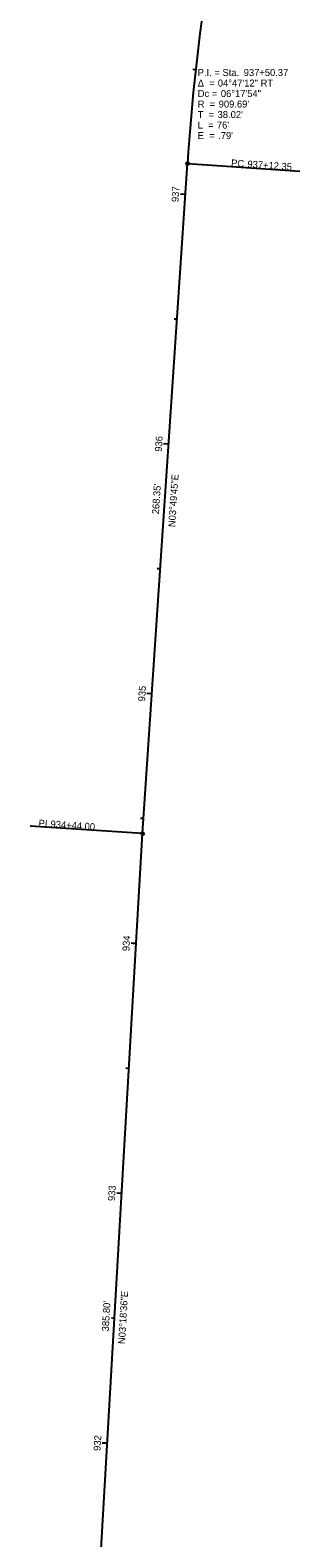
# Model space of a CAD drawing. Extents: x 1978725 to 1979446, y 230316 to 232755.
# Drawn here: x 1978725 to 1978833, y 230920 to 231522 of the extents above; entities that cross this region are included whole.
import ezdxf

# ---------------------------------------------------------------- set-up
doc = ezdxf.new("R2010")
doc.units = 0
for name, color, linetype in [('GE_X_Alignment', 7, 'Continuous'), ('GE_X_Alignment_1000_Curve_Data', 7, 'Continuous'), ('GE_X_Alignment_1000_Stations', 7, 'Continuous'), ('GE_X_Alignment_100_Curve_Data', 7, 'Continuous'), ('GE_X_Alignment_100_Stations', 7, 'Continuous'), ('GE_X_Alignment_500_Curve_Data', 7, 'Continuous'), ('GE_X_Alignment_500_Stations', 7, 'Continuous')]:
    doc.layers.add(name, color=color, linetype=linetype)

msp = doc.modelspace()

# ---------------------------------------------------------------- linework, layer by layer
at = {"layer": 'GE_X_Alignment'}
for p, q in [((1978770.14, 231201.33), (1978788.06, 231469.08)), ((1978747.86, 230816.18), (1978770.14, 231201.33))]:
    msp.add_line(p, q, dxfattribs=at)
msp.add_arc((1979695.72, 231408.33), 909.69, 171.38409, 176.17086, dxfattribs=at)
at = {"layer": 'GE_X_Alignment_1000_Stations'}
for p, q in [((1978788.06, 231469.08), (1978832.96, 231466.08)), ((1978773.88, 231257.2), (1978772.68, 231257.28)), ((1978770.14, 231201.33), (1978725.24, 231204.33))]:
    msp.add_line(p, q, dxfattribs=at)
for centre in [(1978788.06, 231469.08), (1978770.14, 231201.33)]:
    msp.add_circle(centre, 0.6, dxfattribs=at)
at = {"layer": 'GE_X_Alignment_100_Stations'}
for p, q in [((1978791.35, 231506.58), (1978790.15, 231506.71)), ((1978788.06, 231469.08), (1978832.96, 231466.08)), ((1978787.23, 231456.76), (1978785.24, 231456.89)), ((1978783.89, 231406.87), (1978782.7, 231406.95)), ((1978780.55, 231356.98), (1978778.56, 231357.11)), ((1978777.21, 231307.09), (1978776.02, 231307.17)), ((1978773.88, 231257.2), (1978771.88, 231257.34)), ((1978770.54, 231207.32), (1978769.34, 231207.4)), ((1978770.14, 231201.33), (1978725.24, 231204.33)), ((1978767.6, 231157.4), (1978765.6, 231157.52)), ((1978764.71, 231107.49), (1978763.51, 231107.56)), ((1978761.82, 231057.57), (1978759.83, 231057.68)), ((1978758.93, 231007.65), (1978757.74, 231007.72)), ((1978756.05, 230957.74), (1978754.05, 230957.85))]:
    msp.add_line(p, q, dxfattribs=at)
for centre in [(1978788.06, 231469.08), (1978770.14, 231201.33)]:
    msp.add_circle(centre, 0.6, dxfattribs=at)
at = {"layer": 'GE_X_Alignment_500_Stations'}
for p, q in [((1978788.06, 231469.08), (1978832.96, 231466.08)), ((1978787.23, 231456.76), (1978786.03, 231456.84)), ((1978780.55, 231356.98), (1978779.36, 231357.06)), ((1978773.88, 231257.2), (1978771.88, 231257.34)), ((1978770.14, 231201.33), (1978725.24, 231204.33)), ((1978767.6, 231157.4), (1978766.4, 231157.47)), ((1978761.82, 231057.57), (1978760.62, 231057.64)), ((1978756.05, 230957.74), (1978754.85, 230957.81))]:
    msp.add_line(p, q, dxfattribs=at)
for centre in [(1978788.06, 231469.08), (1978770.14, 231201.33)]:
    msp.add_circle(centre, 0.6, dxfattribs=at)

# ---------------------------------------------------------------- texts
at = {"layer": 'GE_X_Alignment_1000_Curve_Data'}
for s, p in [('P.I. = Sta. ', (1978792.17, 231504.05)), ('937+50.37', (1978810.54, 231504.05)), ('Δ  = ', (1978792.17, 231499.85)), ('04°47\'12" RT', (1978800.2, 231499.85)), ('Dc = ', (1978792.17, 231495.65)), ('R  = ', (1978792.17, 231491.45)), ("909.69'", (1978800.54, 231491.45)), ('06°17\'54"', (1978801.41, 231495.65)), ('T  = ', (1978792.17, 231487.25)), ("38.02'", (1978800.11, 231487.25)), ('L  = ', (1978792.17, 231483.05)), ("76'", (1978799.82, 231483.05)), ('E  = ', (1978792.17, 231478.85)), (".79'", (1978800.33, 231478.85))]:
    msp.add_text(s, height=2.8, dxfattribs=at).set_placement(p)
at = {"layer": 'GE_X_Alignment_1000_Stations'}
for s, rotation, p in [('PC', 356.17086, (1978805.43, 231467.97)), ('937+12.35', 356.17086, (1978811.94, 231467.53)), ('N03°49\'45"E', 86.17086, (1978783.14, 231323.73)), ("268.35'", 86.17086, (1978776.67, 231328.87)), ('PI', 356.17086, (1978728.53, 231204.16)), ('934+44.00', 356.17086, (1978733.3, 231203.84)), ('N03°18\'36"E', 86.68999, (1978763.14, 230997.31)), ("385.80'", 86.68999, (1978756.63, 231002.39))]:
    msp.add_text(s, height=2.8, rotation=rotation, dxfattribs=at).set_placement(p)
at = {"layer": 'GE_X_Alignment_100_Curve_Data'}
for s, p in [('P.I. = Sta. ', (1978792.17, 231504.05)), ('937+50.37', (1978810.54, 231504.05)), ('Δ  = ', (1978792.17, 231499.85)), ('04°47\'12" RT', (1978800.2, 231499.85)), ('Dc = ', (1978792.17, 231495.65)), ('R  = ', (1978792.17, 231491.45)), ("909.69'", (1978800.54, 231491.45)), ('06°17\'54"', (1978801.41, 231495.65)), ('T  = ', (1978792.17, 231487.25)), ("38.02'", (1978800.11, 231487.25)), ('L  = ', (1978792.17, 231483.05)), ("76'", (1978799.82, 231483.05)), ('E  = ', (1978792.17, 231478.85)), (".79'", (1978800.33, 231478.85))]:
    msp.add_text(s, height=2.8, dxfattribs=at).set_placement(p)
at = {"layer": 'GE_X_Alignment_100_Stations'}
for s, rotation, p in [('PC', 356.17086, (1978805.43, 231467.97)), ('937+12.35', 356.17086, (1978811.94, 231467.53)), ('937', 86.17086, (1978784.47, 231453.6)), ('936', 86.17086, (1978777.79, 231353.87)), ('N03°49\'45"E', 86.17086, (1978783.14, 231323.73)), ("268.35'", 86.17086, (1978776.67, 231328.87)), ('935', 86.17086, (1978771.11, 231254.09)), ('PI', 356.17086, (1978728.53, 231204.16)), ('934+44.00', 356.17086, (1978733.3, 231203.84)), ('934', 86.68999, (1978764.87, 231154.32)), ('933', 86.68999, (1978759.09, 231054.46)), ('N03°18\'36"E', 86.68999, (1978763.14, 230997.31)), ("385.80'", 86.68999, (1978756.63, 231002.39)), ('932', 86.68999, (1978753.32, 230954.62))]:
    msp.add_text(s, height=2.8, rotation=rotation, dxfattribs=at).set_placement(p)
at = {"layer": 'GE_X_Alignment_500_Curve_Data'}
for s, p in [('P.I. = Sta. ', (1978792.17, 231504.05)), ('937+50.37', (1978810.54, 231504.05)), ('Δ  = ', (1978792.17, 231499.85)), ('04°47\'12" RT', (1978800.2, 231499.85)), ('Dc = ', (1978792.17, 231495.65)), ('R  = ', (1978792.17, 231491.45)), ("909.69'", (1978800.54, 231491.45)), ('06°17\'54"', (1978801.41, 231495.65)), ('T  = ', (1978792.17, 231487.25)), ("38.02'", (1978800.11, 231487.25)), ('L  = ', (1978792.17, 231483.05)), ("76'", (1978799.82, 231483.05)), ('E  = ', (1978792.17, 231478.85)), (".79'", (1978800.33, 231478.85))]:
    msp.add_text(s, height=2.8, dxfattribs=at).set_placement(p)
at = {"layer": 'GE_X_Alignment_500_Stations'}
for s, rotation, p in [('PC', 356.17086, (1978805.43, 231467.97)), ('937+12.35', 356.17086, (1978811.94, 231467.53)), ('N03°49\'45"E', 86.17086, (1978783.14, 231323.73)), ("268.35'", 86.17086, (1978776.67, 231328.87)), ('935', 86.17086, (1978771.11, 231254.09)), ('PI', 356.17086, (1978728.53, 231204.16)), ('934+44.00', 356.17086, (1978733.3, 231203.84)), ('N03°18\'36"E', 86.68999, (1978763.14, 230997.31)), ("385.80'", 86.68999, (1978756.63, 231002.39))]:
    msp.add_text(s, height=2.8, rotation=rotation, dxfattribs=at).set_placement(p)

doc.saveas('drawing.dxf')
